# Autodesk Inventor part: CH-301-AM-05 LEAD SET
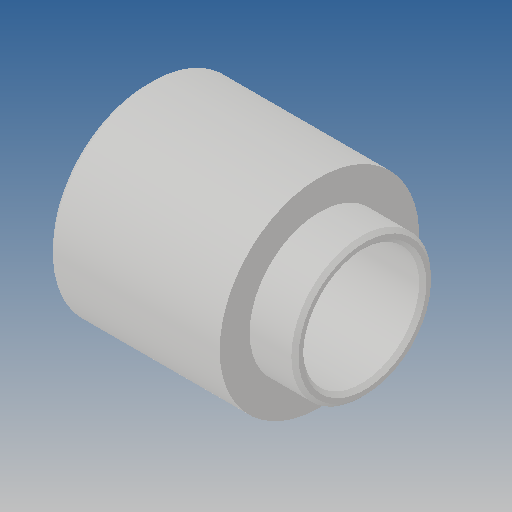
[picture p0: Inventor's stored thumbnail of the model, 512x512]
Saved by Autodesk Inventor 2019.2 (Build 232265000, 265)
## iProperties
Created: 2012-09
Part Number: CH-301-AM-05 LEAD SET
Material: Ogólny
Document SubType Name: Modeling
Designer: CADENGINEERING4
Density: 1 g/cm^3
Appearance: Domyślna
Author: CADENGINEERING4
Revision Number: ÈÎºÎ
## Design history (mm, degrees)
feature "µ¹½Ç3"
node "Bryła1"
